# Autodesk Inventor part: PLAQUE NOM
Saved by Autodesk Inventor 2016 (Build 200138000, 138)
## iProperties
Created: 2013-11
Part Number: PLAQUE NOM
Material: Générique
Document SubType Name: Modeling
Designer: Bruno
Density: 1 g/cm^3
Appearance: Par défaut
Author: Bruno
Sending System: SolidWorks 2013
Last Author: christophe
Last Saved: 2014-02-15
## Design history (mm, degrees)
feature "Enlèv. mat.-Extru.1"
node "Solide1"
